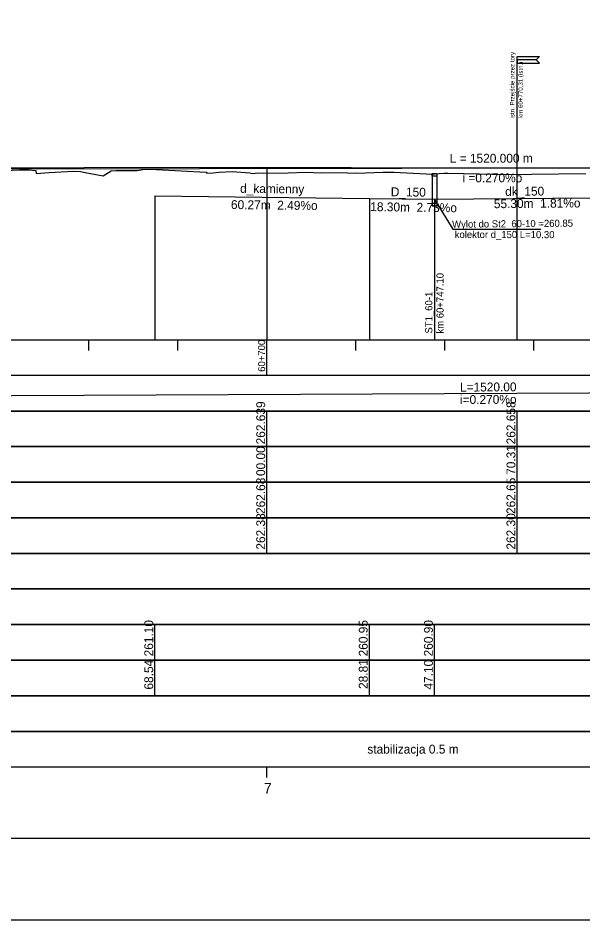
# Model space of a CAD drawing. Extents: x 6445630 to 6518227, y 5499240 to 5511716.
# Drawn here: x 6459861.3 to 6460020, y 5508966.7 to 5509220.2 of the extents above; entities that cross this region are included whole.
import ezdxf

# ---------------------------------------------------------------- set-up
doc = ezdxf.new("R2010")
doc.units = 0
for name, color, linetype in [('Default', 7, 'Continuous'), ('TOR_PROF-drenaze', 7, 'Continuous'), ('TOR_PROF-drenokolektory', 7, 'Continuous'), ('TOR_PROF-obiekty+opisy', 7, 'Continuous'), ('TOR_PROF-opisy glowne', 7, 'Continuous'), ('TOR_PROF-opisy pomocnicze', 7, 'Continuous'), ('TOR_PROF-studnie i osadniki', 7, 'Continuous'), ('TOR_PROF-tabelka-geometria T1', 7, 'Continuous'), ('TOR_PROF-tabelka-kilometracja', 7, 'Continuous'), ('TOR_PROF-tabelka-odleglosci T1', 7, 'Continuous'), ('TOR_PROF-tabelka-pochylenia proj T1', 7, 'Continuous'), ('TOR_PROF-tabelka-rodzaj rowu T1', 7, 'Continuous'), ('TOR_PROF-tabelka-rodzaj rurociagow T1', 7, 'Continuous'), ('TOR_PROF-tabelka-rowyT1', 7, 'Continuous'), ('TOR_PROF-tabelka-rurociagi T1', 7, 'Continuous'), ('TOR_PROF-tabelka-rzedne istn T1', 7, 'Continuous'), ('TOR_PROF-tabelka-rzedne proj T1', 7, 'Continuous'), ('TOR_PROF-tabelka-teren istniejacy T1', 7, 'Continuous'), ('TOR_PROF-tabelka-warstwa ochronna T1', 7, 'Continuous'), ('TOR_PROF-tor istniejacy T1', 7, 'Continuous'), ('TOR_PROF-tor projektowany', 7, 'Continuous'), ('TOR_PROF-uklad odniesienia', 7, 'Continuous'), ('TOR_PROF-warstwa ochronna', 7, 'Continuous'), ('TOR_RAMKI-dodatkowe3', 7, 'Continuous'), ('TOR_RAMKI-MASKA WYCIECIA', 7, 'Continuous')]:
    doc.layers.add(name, color=color, linetype=linetype)

msp = doc.modelspace()

# ---------------------------------------------------------------- linework, layer by layer
at = {"layer": 'TOR_PROF-drenaze'}
for points in [[(6459899.75, 5509170.24), (6459960.02, 5509169.49)], [(6459960.02, 5509169.49), (6459978.32, 5509169.24)], [(6459978.32, 5509169.24), (6460033.52, 5509169.74)]]:
    msp.add_lwpolyline(points, dxfattribs=at)
at = {"layer": 'TOR_PROF-drenokolektory'}
for points in [[(6459899.75, 5509170.24), (6459899.75, 5509134.74), (6459899.75, 5509129.74), (6459899.75, 5509129.74)], [(6459899.75, 5509170.24), (6459899.75, 5509134.74), (6459899.75, 5509129.74), (6459899.75, 5509129.74)], [(6459960.02, 5509169.49), (6459960.02, 5509134.74), (6459960.02, 5509129.74), (6459960.02, 5509129.74)], [(6459960.02, 5509169.49), (6459960.02, 5509134.74), (6459960.02, 5509129.74), (6459960.02, 5509129.74)], [(6459960.02, 5509169.49), (6459960.02, 5509134.74), (6459960.02, 5509129.74), (6459960.02, 5509129.74)], [(6459978.32, 5509169.24), (6459978.32, 5509134.74), (6459978.32, 5509129.74), (6459978.32, 5509129.74)], [(6459978.32, 5509169.24), (6459978.32, 5509134.74), (6459978.32, 5509129.74), (6459978.32, 5509129.74)], [(6459978.32, 5509169.24), (6459978.32, 5509134.74), (6459978.32, 5509129.74), (6459978.32, 5509129.74)]]:
    msp.add_lwpolyline(points, dxfattribs=at)
at = {"layer": 'TOR_PROF-obiekty+opisy'}
for p, q in [((6460001.52, 5509129.74), (6460001.52, 5509209.33)), ((6459978.33, 5509169.16), (6459983.48, 5509160.84)), ((6459983.48, 5509160.84), (6460008.13, 5509160.84))]:
    msp.add_line(p, q, dxfattribs=at)
for points in [[(6460007.77, 5509209.33), (6460006.84, 5509208.39), (6460001.52, 5509208.39), (6460001.52, 5509209.33), (6460007.77, 5509209.33)], [(6460007.77, 5509207.46), (6460006.84, 5509208.39), (6460001.52, 5509208.39), (6460001.52, 5509207.46), (6460007.77, 5509207.46)]]:
    msp.add_lwpolyline(points, dxfattribs=at)
at = {"layer": 'TOR_PROF-studnie i osadniki'}
for p, q in [((6459977.67, 5509176.44), (6459977.67, 5509167.44)), ((6459977.67, 5509176.44), (6459978.97, 5509176.44)), ((6459978.97, 5509176.44), (6459978.97, 5509167.44)), ((6459977.67, 5509167.44), (6459978.97, 5509167.44))]:
    msp.add_line(p, q, dxfattribs=at)
for points in [[(6459977.67, 5509176.44), (6459978.97, 5509176.44), (6459978.97, 5509175.74), (6459977.67, 5509175.74)], [(6459977.67, 5509168.14), (6459978.97, 5509168.14), (6459978.97, 5509167.44), (6459977.67, 5509167.44)]]:
    msp.add_lwpolyline(points, close=True, dxfattribs=at)
at = {"layer": 'TOR_PROF-tabelka-geometria T1'}
for points in [[(6452331.21, 5508989.74), (6462728.4, 5508989.74)], [(6452331.21, 5508989.74), (6462731.21, 5508989.74)]]:
    msp.add_lwpolyline(points, dxfattribs=at)
at = {"layer": 'TOR_PROF-tabelka-kilometracja'}
msp.add_lwpolyline([(6459931.21, 5509006.74), (6459931.21, 5509009.74)], dxfattribs=at)
at = {"layer": 'TOR_PROF-tabelka-odleglosci T1'}
for points in [[(6459931.21, 5509099.74), (6459931.21, 5509109.74)], [(6460001.52, 5509099.74), (6460001.52, 5509109.74)], [(6459931.21, 5509089.74), (6459931.21, 5509099.74)], [(6460001.52, 5509089.74), (6460001.52, 5509099.74)]]:
    msp.add_lwpolyline(points, dxfattribs=at)
msp.add_lwpolyline([(6452331.21, 5509089.74), (6462731.21, 5509089.74), (6462731.21, 5509099.74), (6452331.21, 5509099.74)], close=True, dxfattribs=at)
at = {"layer": 'TOR_PROF-tabelka-pochylenia proj T1'}
msp.add_lwpolyline([(6452331.21, 5509109.74), (6462731.21, 5509109.74), (6462731.21, 5509119.74), (6452331.21, 5509119.74)], close=True, dxfattribs=at)
msp.add_lwpolyline([(6459231.21, 5509111.24), (6460751.21, 5509118.24)], dxfattribs=at)
at = {"layer": 'TOR_PROF-tabelka-rodzaj rowu T1'}
for points in [[(6452331.21, 5509049.74), (6462731.21, 5509049.74), (6462731.21, 5509059.74), (6452331.21, 5509059.74)], [(6452331.21, 5509029.74), (6462731.21, 5509029.74), (6462731.21, 5509039.74), (6452331.21, 5509039.74)]]:
    msp.add_lwpolyline(points, close=True, dxfattribs=at)
for points in [[(6459899.75, 5509029.74), (6459899.75, 5509039.74)], [(6459960.02, 5509029.74), (6459960.02, 5509039.74)], [(6459978.32, 5509029.74), (6459978.32, 5509039.74)]]:
    msp.add_lwpolyline(points, dxfattribs=at)
at = {"layer": 'TOR_PROF-tabelka-rowyT1'}
msp.add_lwpolyline([(6452331.21, 5509059.74), (6462731.21, 5509059.74), (6462731.21, 5509069.74), (6452331.21, 5509069.74)], close=True, dxfattribs=at)
at = {"layer": 'TOR_PROF-tabelka-rurociagi T1'}
msp.add_lwpolyline([(6452331.21, 5509039.74), (6462731.21, 5509039.74), (6462731.21, 5509049.74), (6452331.21, 5509049.74)], close=True, dxfattribs=at)
for points in [[(6459899.75, 5509039.74), (6459899.75, 5509049.74)], [(6459960.02, 5509039.74), (6459960.02, 5509049.74)], [(6459978.32, 5509039.74), (6459978.32, 5509049.74)]]:
    msp.add_lwpolyline(points, dxfattribs=at)
at = {"layer": 'TOR_PROF-tabelka-rzedne istn T1'}
msp.add_lwpolyline([(6452331.21, 5509079.74), (6462731.21, 5509079.74), (6462731.21, 5509089.74), (6452331.21, 5509089.74)], close=True, dxfattribs=at)
for points in [[(6459931.21, 5509079.74), (6459931.21, 5509089.74)], [(6460001.52, 5509079.74), (6460001.52, 5509089.74)], [(6459931.21, 5509069.74), (6459931.21, 5509079.74)], [(6459931.21, 5509069.74), (6459931.21, 5509079.74)], [(6459931.21, 5509069.74), (6459931.21, 5509079.74)], [(6459931.21, 5509069.74), (6459931.21, 5509079.74)], [(6459931.21, 5509069.74), (6459931.21, 5509079.74)], [(6460001.52, 5509069.74), (6460001.52, 5509079.74)]]:
    msp.add_lwpolyline(points, dxfattribs=at)
at = {"layer": 'TOR_PROF-tabelka-rzedne proj T1'}
msp.add_lwpolyline([(6452331.21, 5509099.74), (6462731.21, 5509099.74), (6462731.21, 5509109.74), (6452331.21, 5509109.74)], close=True, dxfattribs=at)
at = {"layer": 'TOR_PROF-tabelka-teren istniejacy T1'}
msp.add_lwpolyline([(6452331.21, 5509069.74), (6462731.21, 5509069.74), (6462731.21, 5509079.74), (6452331.21, 5509079.74)], close=True, dxfattribs=at)
msp.add_lwpolyline([(6452331.21, 5509069.74), (6462731.21, 5509069.74), (6462731.21, 5509079.74), (6452331.21, 5509079.74)], close=True, dxfattribs=at)
msp.add_lwpolyline([(6452331.21, 5509069.74), (6462731.21, 5509069.74), (6462731.21, 5509079.74), (6452331.21, 5509079.74)], close=True, dxfattribs=at)
msp.add_lwpolyline([(6452331.21, 5509069.74), (6462731.21, 5509069.74), (6462731.21, 5509079.74), (6452331.21, 5509079.74)], close=True, dxfattribs=at)
msp.add_lwpolyline([(6452331.21, 5509069.74), (6462731.21, 5509069.74), (6462731.21, 5509079.74), (6452331.21, 5509079.74)], close=True, dxfattribs=at)
at = {"layer": 'TOR_PROF-tabelka-warstwa ochronna T1'}
msp.add_lwpolyline([(6452331.21, 5509019.74), (6462731.21, 5509019.74), (6462731.21, 5509029.74), (6452331.21, 5509029.74)], close=True, dxfattribs=at)
at = {"layer": 'TOR_PROF-tor istniejacy T1'}
msp.add_lwpolyline([(6460704.37, 5509178.58), (6460688.84, 5509178.51), (6460647.25, 5509178.18), (6460634.91, 5509178.09), (6460584.94, 5509177.84), (6460534.2, 5509177.64), (6460484.5, 5509177.69), (6460434.32, 5509177.84), (6460384.44, 5509177.94), (6460334.72, 5509177.99), (6460316.15, 5509177.94), (6460285.09, 5509177.99), (6460235.86, 5509177.99), (6460183.29, 5509178.09), (6460134.2, 5509178.09), (6460082.01, 5509178.04), (6460029.92, 5509177.94), (6460018.28, 5509177.99), (6459980.19, 5509177.99), (6459929.59, 5509178.14), (6459879.85, 5509178.04), (6459830.31, 5509177.94)], dxfattribs=at)
at = {"layer": 'TOR_PROF-tor projektowany'}
msp.add_line((6459231.21, 5509176.99), (6460751.21, 5509179.04), dxfattribs=at)
msp.add_line((6459231.21, 5509176.99), (6460751.21, 5509179.04), dxfattribs=at)
msp.add_lwpolyline([(6459931.21, 5509177.93), (6459931.21, 5509134.74), (6459931.21, 5509129.74), (6459931.21, 5509129.74)], dxfattribs=at)
msp.add_lwpolyline([(6459931.21, 5509177.93), (6459931.21, 5509134.74), (6459931.21, 5509129.74), (6459931.21, 5509129.74)], dxfattribs=at)
at = {"layer": 'TOR_PROF-uklad odniesienia'}
for p, q in [((6452331.21, 5509129.74), (6462731.21, 5509129.74)), ((6459881.21, 5509126.74), (6459881.21, 5509129.74)), ((6459906.21, 5509126.74), (6459906.21, 5509129.74)), ((6459931.21, 5509119.74), (6459931.21, 5509129.74)), ((6459956.21, 5509126.74), (6459956.21, 5509129.74)), ((6459981.21, 5509126.74), (6459981.21, 5509129.74)), ((6460006.21, 5509126.74), (6460006.21, 5509129.74))]:
    msp.add_line(p, q, dxfattribs=at)
at = {"layer": 'TOR_PROF-warstwa ochronna'}
msp.add_lwpolyline([(6452331.21, 5509009.74), (6462731.21, 5509009.74), (6462731.21, 5509019.74), (6452331.21, 5509019.74)], close=True, dxfattribs=at)
at = {"layer": 'TOR_RAMKI-dodatkowe3'}
for p, q in [((6459852.56, 5509177.16), (6459861.69, 5509177.52)), ((6459861.69, 5509177.52), (6459864.3, 5509177.51)), ((6459864.3, 5509177.51), (6459866.29, 5509177.35)), ((6459866.29, 5509177.35), (6459866.38, 5509176.49)), ((6459866.38, 5509176.49), (6459870.01, 5509176.8)), ((6459870.01, 5509176.8), (6459876.75, 5509177.16)), ((6459876.75, 5509177.16), (6459878.84, 5509177.02)), ((6459878.84, 5509177.02), (6459880.11, 5509176.78)), ((6459880.11, 5509176.78), (6459885.23, 5509175.79)), ((6459885.23, 5509175.79), (6459887.4, 5509177.25)), ((6459887.4, 5509177.25), (6459888.86, 5509177.36)), ((6459888.86, 5509177.36), (6459894.79, 5509177.34)), ((6459894.79, 5509177.34), (6459896.93, 5509177.66)), ((6459896.93, 5509177.66), (6459900.08, 5509177.63)), ((6459900.08, 5509177.63), (6459914.09, 5509176.89)), ((6459914.09, 5509176.89), (6459914.28, 5509176.54)), ((6459914.28, 5509176.54), (6459916.14, 5509176.7)), ((6459916.14, 5509176.7), (6459917.79, 5509176.84)), ((6459917.79, 5509176.84), (6459921.42, 5509177.08)), ((6459921.42, 5509177.08), (6459926.41, 5509176.67)), ((6459926.41, 5509176.67), (6459927.18, 5509176.46)), ((6459927.18, 5509176.46), (6459928.65, 5509176.63)), ((6459928.65, 5509176.63), (6459930.11, 5509176.61)), ((6459930.11, 5509176.61), (6459937.15, 5509176.71)), ((6459937.15, 5509176.71), (6459941.98, 5509176.86)), ((6459941.98, 5509176.86), (6459946.59, 5509176.67)), ((6459946.59, 5509176.67), (6459951.29, 5509176.74)), ((6459951.29, 5509176.74), (6459956.4, 5509176.62)), ((6459956.4, 5509176.62), (6459963.83, 5509176.83)), ((6459963.83, 5509176.83), (6459964.66, 5509176.85)), ((6459964.66, 5509176.85), (6459966.9, 5509176.85)), ((6459966.9, 5509176.85), (6459975.95, 5509176.36)), ((6459975.95, 5509176.36), (6459976.85, 5509176.33)), ((6459976.85, 5509176.33), (6459981.03, 5509176.61)), ((6459981.03, 5509176.61), (6459982.02, 5509176.58)), ((6459982.02, 5509176.58), (6459994.59, 5509176.29)), ((6459994.59, 5509176.29), (6459995.13, 5509176.29)), ((6459995.13, 5509176.29), (6460000.53, 5509176.22)), ((6460000.53, 5509176.22), (6460005.53, 5509176.33)), ((6460005.53, 5509176.33), (6460020.84, 5509176.5))]:
    msp.add_line(p, q, dxfattribs=at)
at = {"layer": 'TOR_RAMKI-MASKA WYCIECIA'}
msp.add_lwpolyline([(6459211.14, 5508966.75), (6460761.14, 5508966.75), (6460761.14, 5509253.75), (6459211.14, 5509253.75)], close=True, dxfattribs=at)

# ---------------------------------------------------------------- texts
at = {"layer": 'Default'}
for p in [(6459879.85, 5509178.04), (6459929.59, 5509178.14), (6459980.19, 5509177.99), (6460018.28, 5509177.99)]:
    msp.add_text('+', height=0.001, dxfattribs=at).set_placement(p)
at = {"layer": 'TOR_PROF-drenaze'}
for s, rotation, p in [('d_kamienny', 359.287, (6459923.66, 5509171.07)), ('D_150', 359.2171, (6459965.99, 5509170.1)), ('dk_150', 0.519, (6459998.15, 5509170.19)), ('60.27m  2.49%o  ', 359.287, (6459921.09, 5509166.51)), ('55.30m  1.81%o  ', 0.519, (6459994.97, 5509166.73)), ('18.30m  2.73%o  ', 359.2171, (6459960.23, 5509165.92))]:
    msp.add_text(s, height=2.5, rotation=rotation, dxfattribs=at).set_placement(p)
at = {"layer": 'TOR_PROF-obiekty+opisy'}
for s, p in [('istn. Przejście przez tory  ', (6460000.76, 5509191.94)), ('km 60+770,31 (istn.)', (6460003.1, 5509192.11))]:
    msp.add_text(s, height=1.25, rotation=90, dxfattribs=at).set_placement(p)
at = {"layer": 'TOR_PROF-opisy glowne'}
for s, rotation, p in [('Wylot do St2_60-10 =260.85', 0.4945, (6459983.24, 5509161.24)), ('kolektor d_150 L=10.30', 359.8879, (6459983.97, 5509158.36)), ('km 60+747.10', 90, (6459980.84, 5509131.51)), ('ST1_60-1', 90, (6459977.67, 5509131.51))]:
    msp.add_text(s, height=2, rotation=rotation, dxfattribs=at).set_placement(p)
at = {"layer": 'TOR_PROF-opisy pomocnicze'}
for s, p in [('L = 1520.000 m', (6459982.57, 5509179.5)), ('L = 1520.000 m', (6459982.57, 5509179.5)), ('  i =0.270%o', (6459984.28, 5509174)), ('  i =0.270%o', (6459984.28, 5509174))]:
    msp.add_text(s, height=2.5, rotation=0.0773, dxfattribs=at).set_placement(p)
at = {"layer": 'TOR_PROF-tabelka-kilometracja'}
msp.add_text('7', height=3, dxfattribs=at).set_placement((6459930.32, 5509002.24))
at = {"layer": 'TOR_PROF-tabelka-odleglosci T1'}
for s, p in [('262.639', (6459930.71, 5509100.37)), ('262.658', (6460001.02, 5509100.37)), ('00.00', (6459930.71, 5509091.48)), ('70.31', (6460001.02, 5509091.81))]:
    msp.add_text(s, height=2.5, rotation=90, dxfattribs=at).set_placement(p)
at = {"layer": 'TOR_PROF-tabelka-pochylenia proj T1'}
for s, p in [('L=1520.00', (6459985.45, 5509115.21)), ('i=0.270%o', (6459985.45, 5509111.71))]:
    msp.add_text(s, height=2.5, rotation=0.2639, dxfattribs=at).set_placement(p)
at = {"layer": 'TOR_PROF-tabelka-rodzaj rurociagow T1'}
for s, p in [('68.54', (6459899.25, 5509031.48)), ('28.81', (6459959.52, 5509031.65)), ('47.10', (6459977.82, 5509031.48))]:
    msp.add_text(s, height=2.5, rotation=90, dxfattribs=at).set_placement(p)
at = {"layer": 'TOR_PROF-tabelka-rurociagi T1'}
for s, p in [('261.10', (6459899.25, 5509040.8)), ('260.95', (6459959.52, 5509040.8)), ('260.90', (6459977.82, 5509040.8))]:
    msp.add_text(s, height=2.5, rotation=90, dxfattribs=at).set_placement(p)
at = {"layer": 'TOR_PROF-tabelka-rzedne istn T1'}
for s, p in [('262.68', (6459930.71, 5509080.8)), ('262.65', (6460001.02, 5509080.8)), ('262.38', (6459930.71, 5509070.8)), ('262.30', (6460001.02, 5509070.8))]:
    msp.add_text(s, height=2.5, rotation=90, dxfattribs=at).set_placement(p)
at = {"layer": 'TOR_PROF-uklad odniesienia'}
msp.add_text('60+700', height=2, rotation=90, dxfattribs=at).set_placement((6459930.71, 5509120.76))
at = {"layer": 'TOR_PROF-warstwa ochronna'}
msp.add_text('stabilizacja 0.5 m', height=2.5, dxfattribs=at).set_placement((6459959.42, 5509013.49))

doc.saveas('drawing.dxf')
